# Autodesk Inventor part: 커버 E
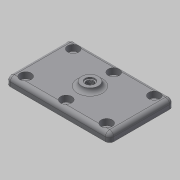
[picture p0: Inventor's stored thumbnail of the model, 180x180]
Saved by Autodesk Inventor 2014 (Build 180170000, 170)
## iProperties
Created: 2020-04
Part Number: 커버 E
Material: 알루미늄 6061
Document SubType Name: Modeling
Designer: mduedu
Density: 2.71 g/cm^3
Appearance: 기본값
Mass: 58.8274 g
Surface Area: 89.9597 cm^2
Volume: 21.7075 cm^3
Author: mduedu
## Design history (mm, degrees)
sketch "스케치1"
  geometry: L1 (37, 23)-(-37, 23); L2 (-37, 23)-(-37, -23); L3 (-37, -23)-(37, -23); L4 (37, -23)-(37, 23); L5 (37, 23)-(-37, -23); L6 (-37, 23)-(37, -23); 1 further point
  constraints: 12 end point, 2 midpoint, 2 parallel, 1 horizontal, 1 perpendicular
  dimensions: "d0" = 74 distance of L3.end L2.end; "d1" = 46 distance of L2.end L1.end
extrude "돌출1" new body sketch "스케치1" distance "d2" = 6; taper "d3" = 0 deg
sketch "스케치2"
  geometry: C1 r 6 at (0, 0); 1 further point
  constraints: 1 centre point, 1 coincident
  dimensions: "d4" = 12 diameter of C1
extrude "돌출2" join sketch "스케치2" distance "d5" = 3; taper "d6" = 0 deg
fillet "모깎기1" dims "d7" = 3
fillet "모깎기2" dims "d8" = 3
fillet "모깎기3" dims "d9" = 3
sketch "스케치3"
  geometry: L1 (-30, -13)-(30, -13); L2 (30, -13)-(30, 13); L3 (30, 13)-(-30, 13); L4 (-30, 13)-(-30, -13); L5 (-30, -13)-(30, 13); L6 (30, -13)-(-30, 13); 1 further point
  constraints: 12 end point, 2 midpoint, 2 parallel, 1 horizontal, 1 perpendicular
  dimensions: "d10" = 60 distance of L3.end L2.end; "d11" = 26 distance of L2.end L1.end
extrude "돌출3" join sketch "스케치3" distance "d12" = 2; taper "d13" = 0 deg
fillet "모깎기4" dims "d14" = 3
chamfer "모따기1" distance "d15" = 0.5; stored, may be unused: second distance "d16" = 2, angle "d17" = 45 deg
sketch "스케치4"
  geometry: L1 (-29, -17)-(29, -17); L2 (29, -17)-(29, 17); L3 (29, 17)-(-29, 17); L4 (-29, 17)-(-29, -17); L5 (-29, -17)-(29, 17); L6 (29, -17)-(-29, 17); 7 further points
  constraints: 12 end point, 4 coincident, 4 midpoint, 2 parallel, 1 horizontal, 1 perpendicular
  dimensions: "d18" = 58 distance of L3.end L2.end; "d19" = 34 distance of L2.end L1.end
hole "구멍1" sketch "스케치4" at (-29, 17), (-29, -17), (29, -17), (29, 17), (0, 17), (0, -17) diameter "d20" = 4.5; stored, may be unused: countersink angle "d24" = 90 deg, drill point angle "d26" = 118 deg; dims "d21" = 6, "d22" = 8, "d23" = 4.4, "d25" = 8
hole "구멍2" diameter "d29" = 5.188; stored, may be unused: countersink angle "d33" = 90 deg, drill point angle "d35" = 118 deg; dims "d27" = 10, "d28" = 10, "d30" = 6, "d31" = 8, "d32" = 4.4, "d34" = 8
sketch "스케치5"
  geometry: C1 r 3.5 at (0, 0); 1 further point
  constraints: 1 centre point, 1 coincident
  dimensions: "d36" = 7 diameter of C1
extrude "돌출4" cut sketch "스케치5" distance "d37" = 1; taper "d38" = 0 deg
node "솔리드1"
